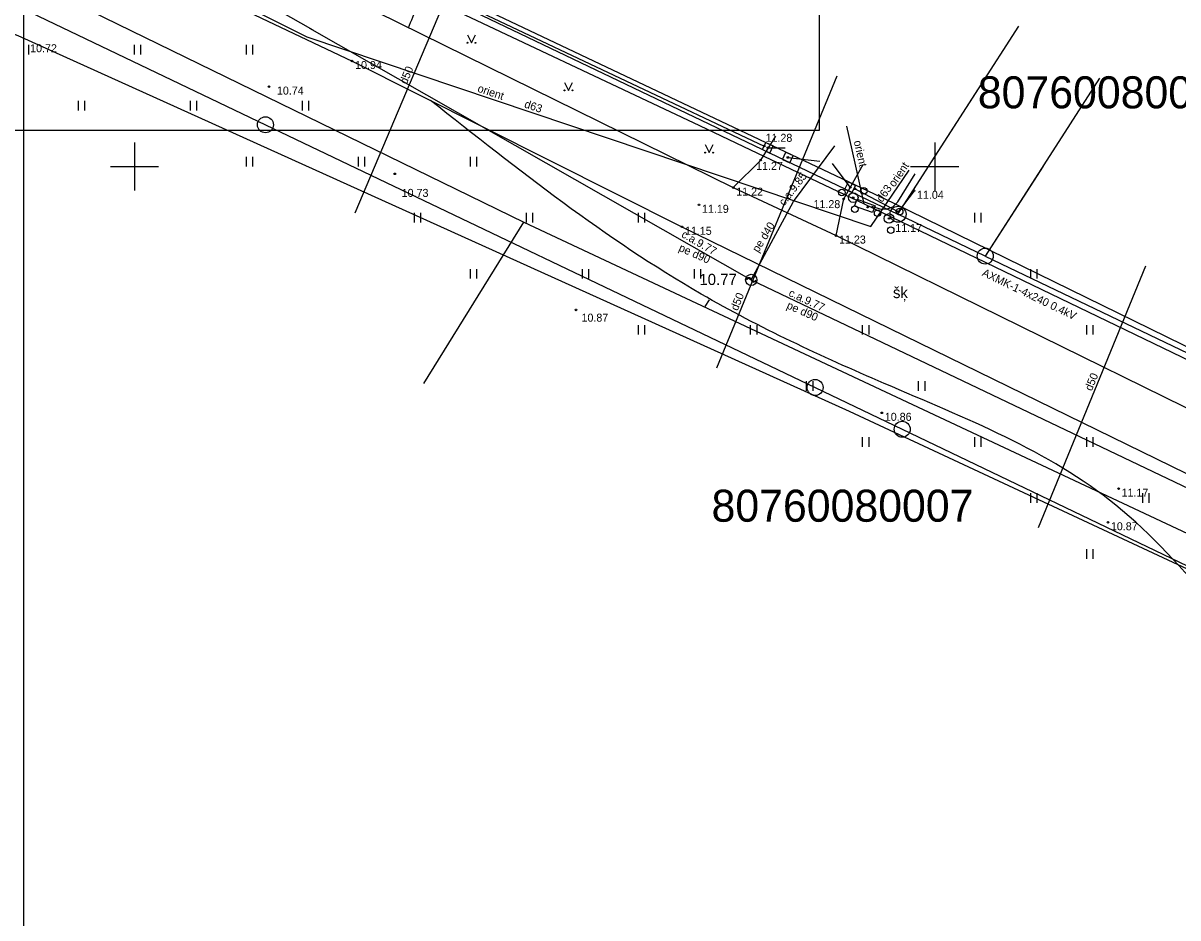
# Model space of a CAD drawing. Extents: x 503353 to 504004, y 304662 to 305049.
# Drawn here: x 503643 to 503715.2, y 304803.1 to 304859 of the extents above; entities that cross this region are included whole.
import ezdxf

# ---------------------------------------------------------------- set-up
doc = ezdxf.new("R2010")
doc.units = 0
for name, color, linetype in [('24', 7, 'Continuous'), ('59', 7, 'Continuous'), ('APGR_ELEM_####_####_#', 7, 'Continuous'), ('APGR_SARK_####_####_#', 7, 'Continuous'), ('CELI_CMAL_####_####_#', 7, 'Continuous'), ('CELI_CSEG_####_TKST_#', 7, 'Continuous'), ('CELI_SEGL_####_####_#', 7, 'Continuous'), ('DREN_VADP_####_####_#', 7, 'Continuous'), ('DREN_VADP_####_TKST_#', 7, 'Continuous'), ('ELEK_ELEM_####_####_#', 7, 'Continuous'), ('ELEK_VADP_ZSPR_####_#', 7, 'Continuous'), ('ELEK_VADP_ZSPR_TKST_#', 7, 'Continuous'), ('GAZE_ELEM_####_####_#', 7, 'Continuous'), ('GAZE_ELEM_####_TKST_#', 7, 'Continuous'), ('GAZE_VADP_VSP1_####_#', 7, 'Continuous'), ('GAZE_VADP_VSP2_####_#', 7, 'Continuous'), ('GAZE_VADP_VSP2_####_I', 7, 'Continuous'), ('GAZE_VADP_VSP2_TKST_#', 7, 'Continuous'), ('GEOD_ELEM_####_####_#', 7, 'Continuous'), ('NORB_ELEM_####_####_#', 7, 'Continuous'), ('NORB_ZOGS_BARJ_####_#', 7, 'Continuous'), ('NORB_ZOGS_ZSTP_####_#', 7, 'Continuous'), ('RAMI_PLAN_####_TKST_#', 7, 'Continuous'), ('RAMI_UZMR_####_####_#', 7, 'Continuous'), ('RELJ_AATZ_####_TKST_#', 7, 'Continuous'), ('RELJ_ELEM_####_####_#', 7, 'Continuous'), ('RELJ_HORZ_PAMT_####_#', 7, 'Continuous'), ('TERT_ELEM_####_####_#', 7, 'Continuous'), ('UDTK_VADP_UDEN_####_#', 7, 'Continuous'), ('UDTK_VADP_UDEN_TKST_#', 7, 'Continuous')]:
    doc.layers.add(name, color=color, linetype=linetype)

msp = doc.modelspace()

# ---------------------------------------------------------------- linework, layer by layer
at = {"layer": '24'}
for p, q in [((503597.271, 304884.111), (503674.34, 304846.523)), ((503697.707, 304847.023), (503702.958, 304855.198)), ((503706.77, 304850.032), (503703.159, 304844.41)), ((503668.078, 304836.442), (503674.34, 304846.523)), ((503674.34, 304846.523), (503724.529, 304822.971)), ((503703.159, 304844.41), (503697.707, 304847.023))]:
    msp.add_line(p, q, dxfattribs=at)
at = {"layer": 'APGR_ELEM_####_####_#'}
for centre in [(503658.19, 304852.61), (503697.71, 304847.02), (503703.16, 304844.41), (503692.53, 304836.2), (503697.97, 304833.59)]:
    msp.add_circle(centre, 0.5, dxfattribs=at)
at = {"layer": 'APGR_SARK_####_####_#'}
for p, q in [((503596.04, 304882.339), (503658.194, 304852.61)), ((503663.371, 304863.436), (503697.707, 304847.023)), ((503697.707, 304847.023), (503705.253, 304858.771)), ((503710.301, 304855.529), (503703.159, 304844.41)), ((503658.194, 304852.61), (503692.526, 304836.199)), ((503703.159, 304844.41), (503751.845, 304821.074)), ((503692.526, 304836.199), (503697.972, 304833.589)), ((503697.972, 304833.589), (503746.643, 304810.26))]:
    msp.add_line(p, q, dxfattribs=at)
at = {"layer": 'CELI_CMAL_####_####_#'}
for points in [[(503613.299, 304880.595), (503629.802, 304872.768), (503644.109, 304865.856), (503663.603, 304856.591), (503684.211, 304846.236), (503716.62, 304830.397), (503750.714, 304813.753), (503759.331, 304809.396), (503770.944, 304803.486), (503794.752, 304792.108), (503812.819, 304782.96), (503836.268, 304772.627), (503857.062, 304763.632), (503889.596, 304749.28)], [(503632.385, 304876.195), (503646.316, 304868.926), (503665.133, 304859.653), (503687.416, 304848.681)], [(503687.416, 304848.681), (503689.13, 304850.408), (503690.08, 304851.892)], [(503693.839, 304845.691), (503694.319, 304847.976), (503695.541, 304850.121)], [(503693.839, 304845.691), (503716.884, 304834.378), (503754.057, 304816.878), (503763.568, 304812.017), (503796.619, 304795.127), (503820.7, 304783.377)]]:
    msp.add_lwpolyline(points, dxfattribs=at)
at = {"layer": 'CELI_SEGL_####_####_#'}
msp.add_lwpolyline([(503687.416, 304848.681), (503693.839, 304845.691)], dxfattribs=at)
at = {"layer": 'DREN_VADP_####_####_#'}
for points in [[(503663.798, 304847.118), (503670.933, 304863.987)], [(503686.389, 304837.422), (503693.901, 304855.67)], [(503706.497, 304827.463), (503713.192, 304843.795)]]:
    msp.add_lwpolyline(points, dxfattribs=at)
at = {"layer": 'ELEK_ELEM_####_####_#'}
msp.add_lwpolyline([(503695.148, 304847.956), (503696.277, 304847.548), (503696.124, 304847.124), (503694.995, 304847.532)], close=True, dxfattribs=at)
at = {"layer": 'ELEK_VADP_ZSPR_####_#'}
for p, q in [((503695.029, 304850.204), (503694.519, 304852.512)), ((503695.586, 304847.678), (503695.029, 304850.204))]:
    msp.add_line(p, q, dxfattribs=at)
for points in [[(503668.093, 304860.71), (503685.3, 304852.554)], [(503685.3, 304852.554), (503688.936, 304850.83)], [(503688.936, 304850.83), (503695.586, 304847.678)], [(503696.062, 304847.524), (503696.571, 304847.36), (503696.977, 304847.33), (503697.385, 304847.48), (503697.693, 304847.792), (503698.783, 304849.536)], [(503695.586, 304847.678), (503717.755, 304836.999)]]:
    msp.add_lwpolyline(points, dxfattribs=at)
at = {"layer": 'GAZE_ELEM_####_####_#'}
msp.add_circle((503688.537, 304842.922), 0.35, dxfattribs=at)
for centre, start, end in [((503688.397, 304842.921), 0.30336, 180.30336), ((503688.677, 304842.923), 180.30336, 0.30336)]:
    msp.add_arc(centre, 0.14, start, end, dxfattribs=at)
at = {"layer": 'GAZE_VADP_VSP1_####_#'}
msp.add_line((503688.537, 304842.922), (503691.184, 304847.818), dxfattribs=at)
at = {"layer": 'GAZE_VADP_VSP2_####_#'}
for p, q in [((503660.948, 304858.652), (503688.537, 304842.922)), ((503688.537, 304842.922), (503691.184, 304847.818)), ((503688.537, 304842.922), (503750.626, 304813.288))]:
    msp.add_line(p, q, dxfattribs=at)
msp.add_lwpolyline([(503691.184, 304847.818), (503693.771, 304851.296)], dxfattribs=at)
at = {"layer": 'GAZE_VADP_VSP2_####_I'}
msp.add_line((503623.026, 304880.274), (503661.15, 304858.537), dxfattribs=at)
at = {"layer": 'GEOD_ELEM_####_####_#'}
for p, q in [((503650, 304851.5), (503650, 304850)), ((503700, 304851.5), (503700, 304850)), ((503648.5, 304850), (503650, 304850)), ((503650, 304850), (503650, 304848.5)), ((503650, 304850), (503651.5, 304850)), ((503698.5, 304850), (503700, 304850)), ((503700, 304850), (503700, 304848.5)), ((503700, 304850), (503701.5, 304850))]:
    msp.add_line(p, q, dxfattribs=at)
at = {"layer": 'NORB_ELEM_####_####_#'}
for p, q in [((503689.242, 304851.058), (503689.46, 304851.508)), ((503689.46, 304851.508), (503689.91, 304851.29)), ((503689.242, 304851.058), (503689.692, 304850.84)), ((503689.692, 304850.84), (503689.91, 304851.29)), ((503690.493, 304850.449), (503690.708, 304850.9)), ((503690.708, 304850.9), (503691.159, 304850.685)), ((503690.493, 304850.449), (503690.944, 304850.234)), ((503690.944, 304850.234), (503691.159, 304850.685)), ((503694.394, 304848.588), (503694.611, 304849.039)), ((503694.394, 304848.588), (503694.845, 304848.371)), ((503694.611, 304849.039), (503695.062, 304848.822)), ((503694.845, 304848.371), (503695.062, 304848.822))]:
    msp.add_line(p, q, dxfattribs=at)
for centre in [(503689.576, 304851.174), (503690.826, 304850.567), (503694.728, 304848.705)]:
    msp.add_circle(centre, 0.0504, dxfattribs=at)
at = {"layer": 'NORB_ZOGS_BARJ_####_#'}
for p, q in [((503689.576, 304851.174), (503690.655, 304851.174)), ((503690.826, 304850.567), (503692.825, 304850.345)), ((503694.728, 304848.705), (503693.615, 304850.18))]:
    msp.add_line(p, q, dxfattribs=at)
at = {"layer": 'NORB_ZOGS_ZSTP_####_#'}
for points in [[(503633.163, 304877.85), (503663.416, 304863.542), (503689.353, 304851.279)], [(503698.711, 304848.486), (503697.722, 304847.176), (503694.968, 304848.628)]]:
    msp.add_lwpolyline(points, dxfattribs=at)
at = {"layer": 'RAMI_PLAN_####_TKST_#'}
for points in [[(503692.785, 305049.441), (503692.785, 304852.257), (503550.18, 304852.257), (503550.18, 305049.441)], [(503840.281, 304747.19), (503643.096, 304747.19), (503643.096, 304889.794), (503840.281, 304889.794)]]:
    msp.add_lwpolyline(points, close=True, dxfattribs=at)
at = {"layer": 'RAMI_UZMR_####_####_#'}
for points in [[(503407.219, 305023.925), (503368.776, 305020.183), (503379.431, 304977.462), (503383.452, 304957.421), (503396.867, 304960.598), (503416.959, 304959.032), (503433.698, 304951.36), (503608.791, 304871.751), (503642.724, 304858.177), (503694.651, 304834.724), (503842.283, 304765.867)], [(503825.923, 304784.828), (503697.433, 304847.709), (503608.51, 304889.842), (503606.524, 304897.202), (503679.244, 304999.942), (503684.897, 305009.76), (503666.777, 305017.939), (503656.134, 304996.39), (503644.103, 304987.6), (503600.987, 304924.263), (503587.985, 304916.668), (503422.237, 304989.372), (503408.615, 305023.495), (503368.776, 305020.183)]]:
    msp.add_lwpolyline(points, dxfattribs=at)
at = {"layer": 'RELJ_ELEM_####_####_#'}
for centre in [(503663.603, 304856.591), (503658.407, 304854.995), (503689.353, 304851.279), (503689.576, 304851.174), (503689.13, 304850.408), (503690.826, 304850.567), (503666.272, 304849.544), (503687.416, 304848.681), (503694.728, 304848.705), (503695.009, 304848.606), (503694.319, 304847.976), (503694.909, 304848.061), (503698.711, 304848.486), (503685.276, 304847.61), (503695.82, 304847.465), (503697.722, 304847.176), (503697.15, 304846.757), (503684.211, 304846.236), (503693.839, 304845.691), (503677.593, 304841.047), (503696.699, 304834.62), (503711.491, 304829.883), (503710.823, 304827.783)]:
    msp.add_circle(centre, 0.05, dxfattribs=at)
at = {"layer": 'RELJ_HORZ_PAMT_####_#'}
msp.add_line((503685.664, 304841.253), (503685.941, 304841.669), dxfattribs=at)
for points in [[(503667.131, 304858.669), (503667.662, 304859.985), (503668.854, 304862.443)], [(503717.475, 304822.613), (503711.324, 304828.85), (503696.839, 304836.46), (503685.418, 304842.03), (503668.505, 304854.128)]]:
    msp.add_spline(points, degree=3, dxfattribs=at)
at = {"layer": 'TERT_ELEM_####_####_#'}
for p, q in [((503670.806, 304858.231), (503671.056, 304857.731)), ((503671.056, 304857.731), (503671.306, 304858.231)), ((503643.4, 304857), (503643.4, 304857.6)), ((503650, 304857), (503650, 304857.6)), ((503650.4, 304857), (503650.4, 304857.6)), ((503657, 304857), (503657, 304857.6)), ((503657.4, 304857), (503657.4, 304857.6)), ((503676.874, 304855.258), (503677.124, 304854.758)), ((503677.124, 304854.758), (503677.374, 304855.258)), ((503646.5, 304853.5), (503646.5, 304854.1)), ((503646.9, 304853.5), (503646.9, 304854.1)), ((503653.5, 304853.5), (503653.5, 304854.1)), ((503653.9, 304853.5), (503653.9, 304854.1)), ((503660.5, 304853.5), (503660.5, 304854.1)), ((503660.9, 304853.5), (503660.9, 304854.1)), ((503685.66, 304851.368), (503685.91, 304850.868)), ((503685.91, 304850.868), (503686.16, 304851.368)), ((503657, 304850), (503657, 304850.6)), ((503657.4, 304850), (503657.4, 304850.6)), ((503664, 304850), (503664, 304850.6)), ((503664.4, 304850), (503664.4, 304850.6)), ((503671, 304850), (503671, 304850.6)), ((503671.4, 304850), (503671.4, 304850.6)), ((503667.5, 304846.5), (503667.5, 304847.1)), ((503667.9, 304846.5), (503667.9, 304847.1)), ((503674.5, 304846.5), (503674.5, 304847.1)), ((503674.9, 304846.5), (503674.9, 304847.1)), ((503681.5, 304846.5), (503681.5, 304847.1)), ((503681.9, 304846.5), (503681.9, 304847.1)), ((503702.5, 304846.5), (503702.5, 304847.1)), ((503702.9, 304846.5), (503702.9, 304847.1)), ((503671, 304843), (503671, 304843.6)), ((503671.4, 304843), (503671.4, 304843.6)), ((503678, 304843), (503678, 304843.6)), ((503678.4, 304843), (503678.4, 304843.6)), ((503685, 304843), (503685, 304843.6)), ((503685.4, 304843), (503685.4, 304843.6)), ((503706, 304843), (503706, 304843.6)), ((503706.4, 304843), (503706.4, 304843.6)), ((503681.5, 304839.5), (503681.5, 304840.1)), ((503681.9, 304839.5), (503681.9, 304840.1)), ((503688.5, 304839.5), (503688.5, 304840.1)), ((503688.9, 304839.5), (503688.9, 304840.1)), ((503695.5, 304839.5), (503695.5, 304840.1)), ((503695.9, 304839.5), (503695.9, 304840.1)), ((503709.5, 304839.5), (503709.5, 304840.1)), ((503709.9, 304839.5), (503709.9, 304840.1)), ((503692, 304836), (503692, 304836.6)), ((503692.4, 304836), (503692.4, 304836.6)), ((503699, 304836), (503699, 304836.6)), ((503699.4, 304836), (503699.4, 304836.6)), ((503695.5, 304832.5), (503695.5, 304833.1)), ((503695.9, 304832.5), (503695.9, 304833.1)), ((503702.5, 304832.5), (503702.5, 304833.1)), ((503702.9, 304832.5), (503702.9, 304833.1)), ((503709.5, 304832.5), (503709.5, 304833.1)), ((503709.9, 304832.5), (503709.9, 304833.1)), ((503706, 304829), (503706, 304829.6)), ((503706.4, 304829), (503706.4, 304829.6)), ((503713, 304829), (503713, 304829.6)), ((503713.4, 304829), (503713.4, 304829.6)), ((503709.5, 304825.5), (503709.5, 304826.1)), ((503709.9, 304825.5), (503709.9, 304826.1))]:
    msp.add_line(p, q, dxfattribs=at)
for centre, radius in [((503670.805, 304857.731), 0.028), ((503671.305, 304857.731), 0.0263), ((503676.874, 304854.758), 0.028), ((503677.374, 304854.758), 0.0263), ((503685.66, 304850.868), 0.028), ((503686.16, 304850.868), 0.0263), ((503694.195, 304848.385), 0.204), ((503695.57, 304848.486), 0.207), ((503694.909, 304848.061), 0.301), ((503695.012, 304847.333), 0.205), ((503696.436, 304847.081), 0.204), ((503697.811, 304847.182), 0.207), ((503697.15, 304846.757), 0.301), ((503697.253, 304846.029), 0.205)]:
    msp.add_circle(centre, radius, dxfattribs=at)
at = {"layer": 'UDTK_VADP_UDEN_####_#'}
for points in [[(503600.655, 304888.132), (503660.783, 304858.093)], [(503660.783, 304858.093), (503696.015, 304846.258), (503698.411, 304849.769)]]:
    msp.add_lwpolyline(points, dxfattribs=at)

# ---------------------------------------------------------------- texts
at = {"layer": '59'}
for s, p in [('80760080083', (503702.696, 304853.636)), ('80760080007', (503686.06, 304827.817))]:
    msp.add_text(s, height=2, dxfattribs=at).set_placement(p)
at = {"layer": 'CELI_CSEG_####_TKST_#'}
msp.add_text('šķ', height=0.7, dxfattribs=at).set_placement((503697.394, 304841.783))
at = {"layer": 'DREN_VADP_####_TKST_#'}
for rotation, p in [(67.07097, (503667.012, 304855.103)), (67.62717, (503687.682, 304840.957)), (67.71051, (503709.812, 304835.944))]:
    msp.add_text('d50', height=0.5, rotation=rotation, dxfattribs=at).set_placement(p)
at = {"layer": 'ELEK_VADP_ZSPR_TKST_#'}
for s, rotation, p in [('orient.', 282.44484, (503694.942, 304851.577)), ('AXMK-1-4x240 0.4kV', 334.20173, (503702.915, 304843.201))]:
    msp.add_text(s, height=0.5, rotation=rotation, dxfattribs=at).set_placement(p)
at = {"layer": 'GAZE_ELEM_####_TKST_#'}
msp.add_text('10.77', height=0.7, rotation=0.30338, dxfattribs=at).set_placement((503685.302, 304842.597))
at = {"layer": 'GAZE_VADP_VSP2_TKST_#'}
for s, rotation, p in [('c.a.9.85', 52.23571, (503690.599, 304847.51)), ('pe d40', 58.58687, (503688.982, 304844.592)), ('c.a.9.77', 330.24352, (503684.133, 304845.625)), ('pe d90', 335.99561, (503683.965, 304844.754)), ('c.a.9.77', 334.92824, (503690.83, 304841.939)), ('pe d90', 335.99561, (503690.707, 304841.158))]:
    msp.add_text(s, height=0.5, rotation=rotation, dxfattribs=at).set_placement(p)
at = {"layer": 'RELJ_AATZ_####_TKST_#'}
for s, p in [('10.72', (503643.487, 304857.139)), (' 10.94', (503663.603, 304856.091)), ('10.74', (503658.907, 304854.495)), (' 11.28', (503689.247, 304851.545)), (' 11.27', (503688.658, 304849.791)), ('10.73', (503666.7, 304848.104)), (' 11.22', (503687.416, 304848.181)), (' 11.28', (503692.243, 304847.401)), (' 11.04', (503698.711, 304847.986)), (' 11.19', (503685.276, 304847.11)), (' 11.17', (503697.351, 304845.911)), (' 11.15', (503684.211, 304845.736)), (' 11.23', (503693.839, 304845.191)), ('10.87', (503677.934, 304840.313)), (' 10.86', (503696.699, 304834.12)), (' 11.17', (503711.491, 304829.383)), (' 10.87', (503710.823, 304827.283))]:
    msp.add_text(s, height=0.5, dxfattribs=at).set_placement(p)
at = {"layer": 'UDTK_VADP_UDEN_TKST_#'}
for s, rotation, p in [('orient', 341.43165, (503671.401, 304854.685)), ('d63', 341.43165, (503674.324, 304853.703)), ('orient', 55.69282, (503697.482, 304848.675)), ('d63', 55.69282, (503696.725, 304847.73))]:
    msp.add_text(s, height=0.5, rotation=rotation, dxfattribs=at).set_placement(p)

doc.saveas('drawing.dxf')
